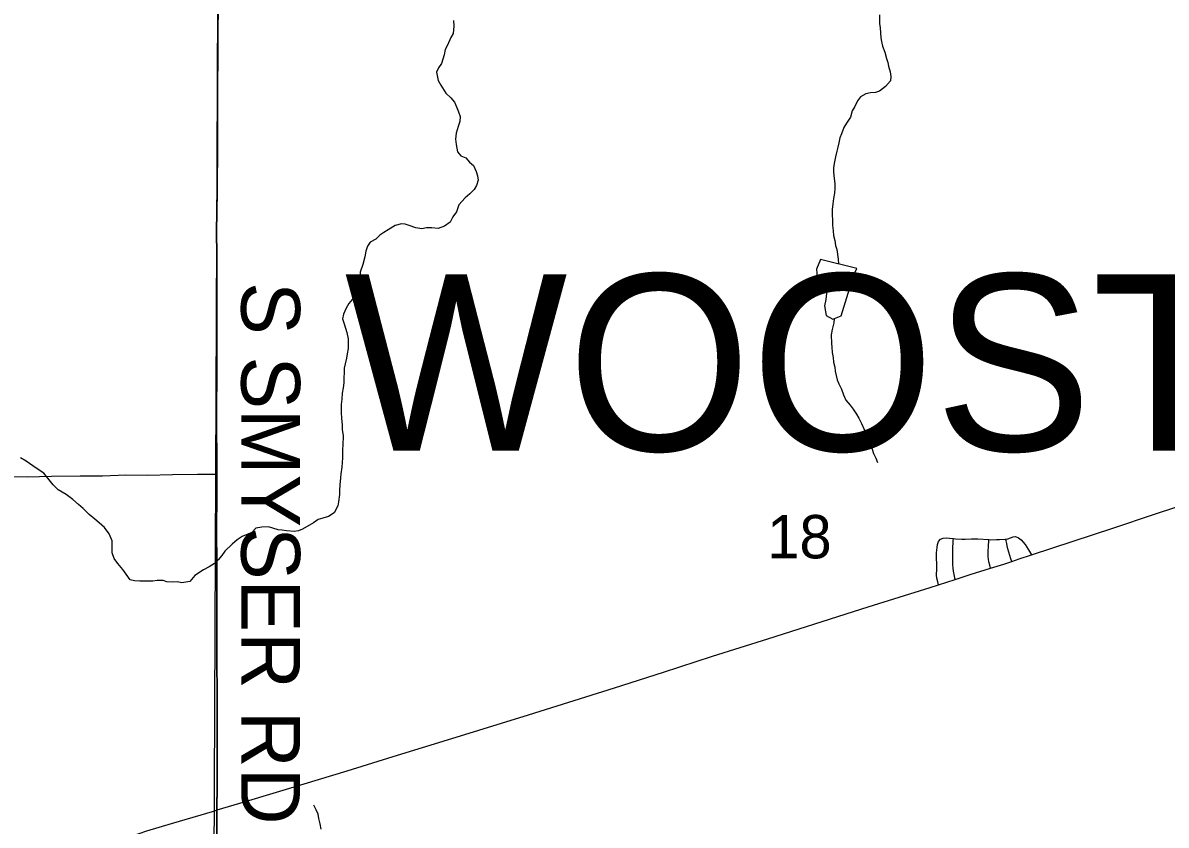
# Model space of a CAD drawing. Extents: x 0 to 34, y 0 to 22.
# Drawn here: x 5.466 to 6.57, y 19.089 to 19.863 of the extents above; entities that cross this region are included whole.
import ezdxf

# ---------------------------------------------------------------- set-up
doc = ezdxf.new("R2010")
doc.units = 0
for name, color, linetype in [('GM_X_Minor_Lake', 7, 'Continuous'), ('GM_X_Minor_River', 7, 'Continuous'), ('GM_X_Section', 7, 'Continuous'), ('GM_X_Section_Text', 7, 'Continuous'), ('GM_X_State_Route', 7, 'Continuous'), ('GM_X_Township_Road', 7, 'Continuous'), ('GM_X_Township_Road_Text', 7, 'Continuous'), ('GM_X_Township_Text', 7, 'Continuous')]:
    doc.layers.add(name, color=color, linetype=linetype)

msp = doc.modelspace()

# ---------------------------------------------------------------- linework, layer by layer
at = {"layer": 'GM_X_Minor_Lake'}
for points in [[(6.2363, 19.6347), (6.2322, 19.6252), (6.2331, 19.6177), (6.2376, 19.6128), (6.2422, 19.6048), (6.2412, 19.5961), (6.2401, 19.59), (6.2416, 19.5806), (6.2481, 19.5772), (6.256, 19.5803), (6.2683, 19.6198), (6.2713, 19.6259)], [(6.2713, 19.6259), (6.2363, 19.6347)]]:
    msp.add_lwpolyline(points, dxfattribs=at)
at = {"layer": 'GM_X_Minor_River'}
for points in [[(5.8817, 19.8652), (5.8821, 19.8599), (5.8815, 19.8527), (5.8792, 19.8489), (5.8759, 19.8416), (5.8737, 19.8374), (5.8726, 19.8321), (5.8701, 19.8237), (5.8671, 19.8195), (5.8652, 19.8153), (5.8669, 19.8073), (5.8696, 19.8028), (5.8742, 19.7952), (5.8792, 19.7908), (5.8827, 19.7866), (5.8847, 19.7821), (5.8866, 19.7772), (5.8882, 19.7726), (5.8879, 19.7677), (5.8864, 19.7631), (5.8842, 19.7566), (5.8836, 19.7509), (5.8844, 19.7456), (5.8856, 19.7384), (5.8887, 19.7347)], [(6.2931, 19.8707), (6.2932, 19.8624), (6.2937, 19.8582), (6.2941, 19.8533), (6.2946, 19.8487), (6.295, 19.8449), (6.2962, 19.8404), (6.2982, 19.8347), (6.2998, 19.8287), (6.3013, 19.8249), (6.3018, 19.8211), (6.3033, 19.8158), (6.3042, 19.8112), (6.3038, 19.8071), (6.299, 19.8017), (6.2933, 19.797), (6.2892, 19.7958), (6.2846, 19.7954), (6.28, 19.7946), (6.2748, 19.7915), (6.2718, 19.7876), (6.2692, 19.7823), (6.2669, 19.7781), (6.2651, 19.772), (6.2614, 19.7662), (6.2588, 19.762), (6.2566, 19.7559), (6.2547, 19.7521), (6.254, 19.7471), (6.253, 19.7429), (6.2519, 19.7391), (6.2508, 19.7338), (6.2494, 19.7273), (6.2486, 19.7231), (6.2487, 19.719), (6.2495, 19.7129), (6.25, 19.708), (6.25, 19.703), (6.2497, 19.6988), (6.2487, 19.6935), (6.248, 19.6882), (6.2476, 19.6829), (6.2479, 19.6673), (6.2483, 19.6624), (6.2487, 19.6578), (6.2499, 19.6529), (6.2508, 19.6483), (6.252, 19.6442), (6.2532, 19.6351), (6.2535, 19.6304)], [(5.8887, 19.7347), (5.8937, 19.7328), (5.8972, 19.7287), (5.901, 19.7253), (5.9037, 19.7197), (5.9049, 19.7155), (5.9054, 19.7113), (5.9039, 19.706), (5.9017, 19.7022), (5.8976, 19.6979), (5.893, 19.6941), (5.887, 19.6875), (5.8845, 19.6807), (5.8811, 19.6757), (5.8785, 19.6707), (5.8732, 19.6668), (5.8668, 19.6645), (5.8607, 19.6652), (5.8558, 19.6651), (5.8512, 19.6643), (5.8455, 19.6653), (5.839, 19.6675), (5.8352, 19.6686), (5.8314, 19.6689), (5.8253, 19.6673), (5.8185, 19.6634), (5.8144, 19.6607), (5.8106, 19.658), (5.8068, 19.6542), (5.8012, 19.6514), (5.7986, 19.6476), (5.7971, 19.6427), (5.796, 19.6373), (5.7942, 19.6297), (5.7917, 19.6224), (5.7913, 19.6179), (5.791, 19.6129), (5.7907, 19.6069), (5.7889, 19.6008), (5.784, 19.5961), (5.7807, 19.5923), (5.778, 19.5877), (5.7755, 19.582), (5.7744, 19.5774), (5.776, 19.5725), (5.7775, 19.5683), (5.7787, 19.5642), (5.78, 19.5581), (5.7801, 19.5486), (5.779, 19.5436), (5.7783, 19.5395), (5.7772, 19.5341), (5.7761, 19.5296), (5.7762, 19.5258), (5.7759, 19.5201), (5.7759, 19.5155), (5.7752, 19.5109), (5.7742, 19.5056), (5.7739, 19.4999), (5.7732, 19.4946), (5.7733, 19.487), (5.7737, 19.4813), (5.7742, 19.4752), (5.7742, 19.4706), (5.7751, 19.4646), (5.7748, 19.4555), (5.7745, 19.4517), (5.7746, 19.4433), (5.774, 19.4342), (5.7729, 19.4277), (5.7726, 19.4239), (5.7719, 19.4171), (5.7716, 19.4117), (5.7716, 19.4079), (5.7706, 19.4007), (5.7699, 19.3969), (5.7665, 19.39), (5.7609, 19.3865), (5.7556, 19.3849), (5.751, 19.3837), (5.7465, 19.3806), (5.7359, 19.3744), (5.7322, 19.3728), (5.728, 19.372), (5.7204, 19.3727), (5.7162, 19.3734), (5.7124, 19.3737), (5.7074, 19.3755), (5.7032, 19.3766), (5.6967, 19.3762), (5.6907, 19.3753), (5.6869, 19.3711), (5.6775, 19.3672), (5.6729, 19.3641), (5.6681, 19.3598), (5.6609, 19.3533), (5.6579, 19.3491), (5.6546, 19.3448), (5.6508, 19.3414), (5.6459, 19.3379), (5.6402, 19.3351)], [(6.2495, 19.5777), (6.2491, 19.5735), (6.2476, 19.567), (6.2466, 19.562), (6.2467, 19.5537), (6.2471, 19.5499), (6.2475, 19.545), (6.2484, 19.54), (6.2488, 19.5355), (6.25, 19.5306), (6.2504, 19.5268), (6.2513, 19.5226), (6.2524, 19.5184), (6.254, 19.5147), (6.2564, 19.5094), (6.2583, 19.5041), (6.2607, 19.4988), (6.2649, 19.4939), (6.2677, 19.4902), (6.2708, 19.4853), (6.2731, 19.4815), (6.2758, 19.4762), (6.2786, 19.4698), (6.2809, 19.466), (6.2825, 19.4615), (6.2837, 19.4573), (6.286, 19.4517), (6.2872, 19.4475), (6.2896, 19.443), (6.2911, 19.4388)], [(5.6402, 19.3351), (5.6319, 19.3297), (5.6271, 19.324), (5.6233, 19.3231), (5.6195, 19.3227), (5.6153, 19.3234), (5.61, 19.3233), (5.605, 19.3237), (5.6012, 19.3247), (5.5955, 19.325), (5.5913, 19.3242), (5.5788, 19.3241), (5.5738, 19.3244), (5.5696, 19.3255), (5.5657, 19.3311), (5.5623, 19.3356), (5.5576, 19.3413), (5.5541, 19.3461), (5.5522, 19.3514), (5.552, 19.3632), (5.5493, 19.37), (5.5446, 19.376), (5.5396, 19.3805), (5.5354, 19.3839), (5.53, 19.3884), (5.5242, 19.3944), (5.5196, 19.3981), (5.5142, 19.403), (5.5077, 19.4078), (5.5, 19.4123), (5.495, 19.4172), (5.4912, 19.422), (5.4861, 19.4284), (5.4796, 19.4325), (5.4754, 19.4355), (5.4689, 19.44), (5.4635, 19.4433)], [(5.7538, 19.0848), (5.753, 19.0901), (5.7517, 19.095), (5.7509, 19.0992), (5.749, 19.1034), (5.747, 19.1079)]]:
    msp.add_lwpolyline(points, dxfattribs=at)
at = {"layer": 'GM_X_Section'}
for points in [[(4.6746, 18.9086), (5.6498, 18.8985), (5.6542, 19.8813), (5.654, 19.9264), (4.6576, 19.9182), (4.6526, 19.2311), (4.6746, 19.2311)], [(5.6542, 19.8813), (6.7799, 19.8913), (6.7847, 18.8752), (5.6499, 18.8708), (5.6498, 18.8985)]]:
    msp.add_lwpolyline(points, close=True, dxfattribs=at)
at = {"layer": 'GM_X_State_Route'}
for points in [[(5.6543, 19.8722), (5.6542, 19.8598), (5.6542, 19.8412), (5.654, 19.8226), (5.6539, 19.8101), (5.6538, 19.7946), (5.6537, 19.7729), (5.6537, 19.7449), (5.6535, 19.7015), (5.6529, 19.6611), (5.6531, 19.6394), (5.6533, 19.6115), (5.6532, 19.5773), (5.6532, 19.5277), (5.653, 19.4873), (5.6531, 19.428), (5.6532, 19.4097), (5.653, 19.3725), (5.6531, 19.3411), (5.6533, 19.3166), (5.6533, 19.27), (5.6535, 19.1924), (5.6535, 19.1272), (5.6533, 19.1039), (5.6532, 19.0901), (5.6531, 19.0435)], [(5.6531, 19.0435), (5.6532, 19.0901), (5.6533, 19.1039), (5.6535, 19.1272), (5.6535, 19.1924), (5.6533, 19.27), (5.6533, 19.3166), (5.6531, 19.3411), (5.653, 19.3725), (5.6532, 19.4097), (5.6531, 19.428), (5.653, 19.4873), (5.6532, 19.5277), (5.6532, 19.5773), (5.6533, 19.6115), (5.6531, 19.6394), (5.6529, 19.6611), (5.6535, 19.7015), (5.6537, 19.7449), (5.6537, 19.7729), (5.6538, 19.7946), (5.6539, 19.8101), (5.654, 19.8226), (5.6542, 19.8412), (5.6542, 19.8598), (5.6543, 19.8722)], [(6.2823, 19.2995), (6.3422, 19.3182), (6.3502, 19.3208), (6.3661, 19.3258), (6.3807, 19.3305), (6.4005, 19.3367), (6.4133, 19.3407), (6.4208, 19.3433), (6.4279, 19.3457), (6.4401, 19.3497), (6.5194, 19.3757), (6.5577, 19.3884), (6.6018, 19.4031)], [(5.6535, 19.1034), (5.681, 19.1115), (5.7375, 19.1287), (5.7791, 19.1413), (5.8236, 19.1551), (5.88, 19.1724), (5.9542, 19.1953), (6.0372, 19.2214), (6.0845, 19.2365), (6.1318, 19.2518), (6.1852, 19.2687), (6.2681, 19.295), (6.2823, 19.2995)], [(5.4752, 19.0193), (5.4928, 19.0339), (5.5076, 19.0453), (5.5177, 19.0525), (5.5256, 19.0575), (5.5338, 19.0621), (5.545, 19.0676), (5.5593, 19.0738), (5.5709, 19.0782), (5.5857, 19.0832), (5.6095, 19.0904), (5.6512, 19.1027), (5.6535, 19.1034)]]:
    msp.add_lwpolyline(points, dxfattribs=at)
at = {"layer": 'GM_X_Township_Road'}
for points in [[(5.6533, 19.4275), (5.6533, 19.4868), (5.6534, 19.5271), (5.6534, 19.5768), (5.6535, 19.6109), (5.6533, 19.6388), (5.6531, 19.6606), (5.6537, 19.7009), (5.6539, 19.7444), (5.6539, 19.7723), (5.654, 19.7941), (5.6541, 19.8096), (5.6542, 19.822), (5.6544, 19.8406), (5.6544, 19.8592), (5.6545, 19.8717), (5.6546, 19.8814)], [(5.45, 19.4252), (5.4704, 19.425), (5.4934, 19.4255), (5.5211, 19.4259), (5.5427, 19.4258), (5.5654, 19.4267), (5.5861, 19.4266), (5.6102, 19.4273), (5.6345, 19.4274), (5.6454, 19.4275), (5.6517, 19.4275), (5.6533, 19.4275)], [(5.6535, 19.1034), (5.6537, 19.1267), (5.6537, 19.1919), (5.6536, 19.2695), (5.6535, 19.316), (5.6533, 19.3406), (5.6532, 19.3719), (5.6534, 19.4092), (5.6533, 19.4275)], [(6.3502, 19.3208), (6.3494, 19.3236), (6.3485, 19.3272), (6.3481, 19.3301), (6.3485, 19.3361), (6.3486, 19.3391), (6.3483, 19.3483), (6.3483, 19.3514), (6.3485, 19.3542), (6.3488, 19.3568), (6.3492, 19.3596), (6.3501, 19.3626), (6.352, 19.3648), (6.3548, 19.3658), (6.3577, 19.366), (6.3607, 19.3658), (6.3645, 19.3654), (6.3667, 19.3651), (6.3728, 19.3646), (6.3759, 19.3646), (6.382, 19.3649), (6.3881, 19.3649), (6.3988, 19.3643), (6.4001, 19.3642), (6.406, 19.3643), (6.4089, 19.3643), (6.4144, 19.3646), (6.415, 19.3647), (6.4172, 19.3651), (6.4197, 19.3659), (6.4221, 19.3669), (6.4246, 19.3672), (6.4274, 19.366), (6.4299, 19.3641), (6.432, 19.3619), (6.4338, 19.3595), (6.4355, 19.3569), (6.4372, 19.3543), (6.4401, 19.3497)], [(6.3661, 19.3258), (6.3652, 19.3306), (6.3646, 19.3338), (6.3642, 19.3369), (6.3641, 19.34), (6.364, 19.349), (6.3639, 19.3521), (6.3639, 19.3551), (6.3643, 19.363), (6.3645, 19.3654)], [(6.4005, 19.3367), (6.3997, 19.3398), (6.3988, 19.3428), (6.3984, 19.3453), (6.3981, 19.348), (6.3981, 19.3509), (6.3981, 19.3539), (6.3983, 19.357), (6.3988, 19.3643)], [(6.4208, 19.3433), (6.42, 19.3459), (6.418, 19.3522), (6.4172, 19.3554), (6.4165, 19.3583), (6.416, 19.3604), (6.4154, 19.3631), (6.415, 19.3647)], [(5.6551, 18.8533), (5.6542, 18.8596), (5.6537, 18.8646), (5.6536, 18.869), (5.6533, 18.8919), (5.6531, 18.904), (5.6532, 18.9188), (5.6536, 18.9685), (5.6535, 19.0026), (5.6533, 19.0429), (5.6534, 19.0895), (5.6535, 19.1034)]]:
    msp.add_lwpolyline(points, dxfattribs=at)

# ---------------------------------------------------------------- texts
at = {"layer": 'GM_X_Section_Text'}
msp.add_text('18', height=0.04186, rotation=0, dxfattribs=at).set_placement((6.1847, 19.3462))
at = {"layer": 'GM_X_Township_Road_Text'}
msp.add_text('S SMYSER RD', height=0.056818, rotation=270, dxfattribs=at).set_placement((5.6767, 19.6128))
at = {"layer": 'GM_X_Township_Text'}
msp.add_text('WOOSTER', height=0.17045, rotation=0, dxfattribs=at).set_placement((5.7766, 19.45))

doc.saveas('drawing.dxf')
